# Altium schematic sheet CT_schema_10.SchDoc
size 147 x 119 mm
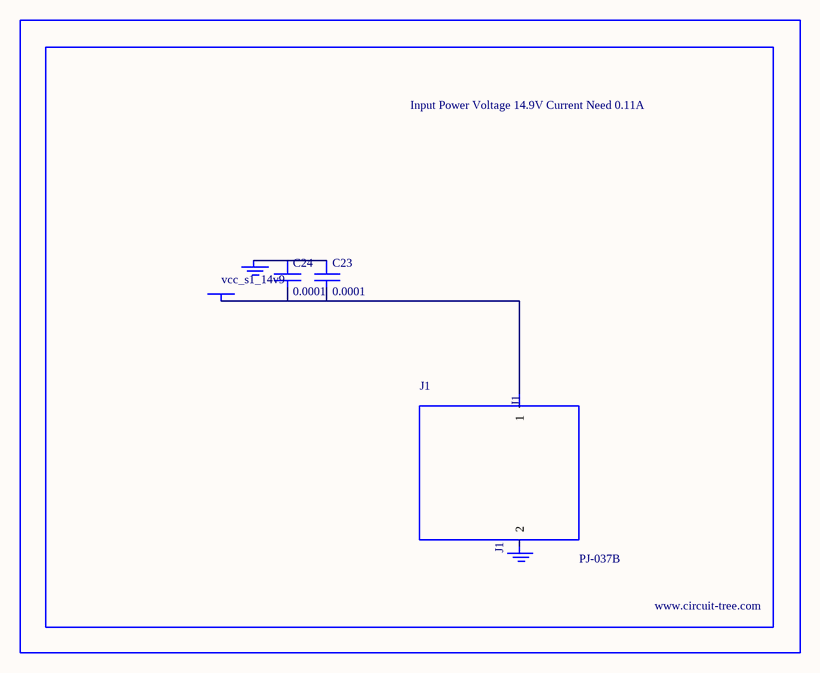
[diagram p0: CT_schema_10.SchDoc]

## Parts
BORDER9  (no value)
C23  0.0001  [EXV-9H]
C24  0.0001  [EXV-9H]
GND_INSTANCE_9_0  (no value)
GND_INSTANCE_9_1  (no value)
J1  PJ-037B  [PJ-037B_PACKAGE]
POWER_INSTANCE_9_0  vcc_s1_14v9

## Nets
NetC23_1: C23.1 C24.1 GND_INSTANCE_9_0.0(GND)
NetC23_2: C23.2 C24.2 J1.1 POWER_INSTANCE_9_0.0(PWR)

Not connected (* = marked no-connect by the designer): GND_INSTANCE_9_1 0(GND); J1 2

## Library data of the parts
BORDER9 = BORDER_PAGE9
C23 C24 = EDK107M035A9HAA
GND_INSTANCE_9_0 GND_INSTANCE_9_1 = GND
POWER_INSTANCE_9_0 = PWR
